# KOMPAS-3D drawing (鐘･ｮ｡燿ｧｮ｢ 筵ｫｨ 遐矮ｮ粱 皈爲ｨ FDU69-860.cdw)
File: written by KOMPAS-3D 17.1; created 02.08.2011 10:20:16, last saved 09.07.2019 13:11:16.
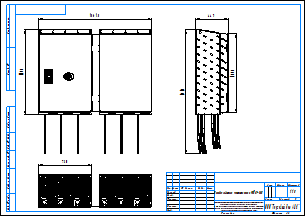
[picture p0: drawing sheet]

Title block, sheet 1: name: Преобразователи частоты серии FDU69-860; scale: 1:10; sheets: 1; sheet format: A3; stored path: \\adlc.lan\data\АДЛ_ПКД\3D-модели\Поставщики\Оборудование Emotron\Преобразователи частоты\Серия FDU 2.0\KOMPAS 2D\Преобразователи частоты серии FDU69-860.cdw

Views: Спереди 1
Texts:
  Рама для чертежей
  Лит-Масса-Масштаб
  Материал-Предприятие
  Масштаб
  Изм.
  Лист
  № докум.
  Подп.
  Дата
  Лит.
  Разраб.
  Пров.
  Т.контр.
  Листов
  Внимание! Данный продукт является объектом авторского права ООО «Торговый Дом АДЛ».
  Запрещается изменение, копирование, распространение
  (в том числе путем копирования на другие сайты и ресурсы в Интернете)
  или любое иное использование информации и объектов без предварительного
  согласия правообладателя (ООО «Торговый Дом АДЛ»).
  Н.контр.
  Утв.
  ООО "Торговый дом АДЛ"
  Изменение
  Номер документа
  Подпись
  Обозначение документа
  Наименование изделия
  Масса изделия по ГОСТ 2.109-73
  Порядковый номер листа
  Общее количество листов в документе
  Характер работы, выполненной лицом, подписавшим документ
  Наименование или индекс предприятия, выпускающего документ
  Инв. № подл.
  Подп. и дата
  Взам. инв. №
  Инв. № дубл.
  Инвентарный номер подлинника по ГОСТ 2.501-68
  Подпись принявшего подлинник в отдел технической документации
  Инвентарный номер подлинника, взамен которого выпущен данный подлинник
  Инвентарный номер дубликата по ГОСТ 2.502-68
  Подпись принявшего дубликат в отдел технической документации
  Справ. №
  Перв. примен.
  Обозначение документа, взамен или на основании которого выпущен данный документ
  Обозначение документа, в котором впервые записан данный документ
  Подпись лица, копировавшего чертеж
  Обозначение формата листа
  !Рама для чертежа
Dimensions and other numbers on the sheet: 1561,5; 1176; 730; 1718; 1096; 449; 1:10; 1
